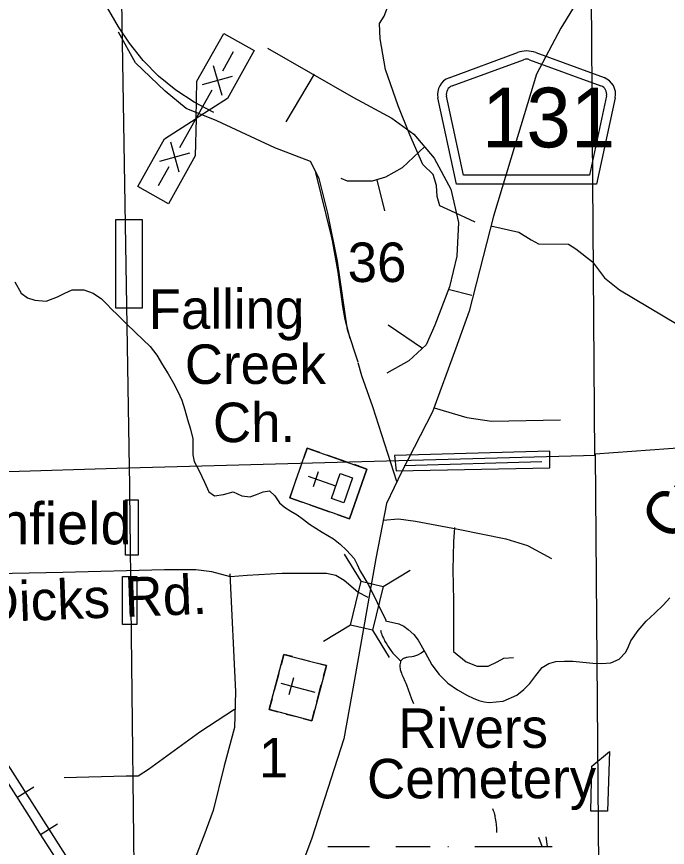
# Model space of a CAD drawing. Extents: x 2480962 to 2688785, y 277103 to 599240.
# Drawn here: x 2542680 to 2550088, y 460329 to 469792 of the extents above; entities that cross this region are included whole.
import ezdxf

# ---------------------------------------------------------------- set-up
doc = ezdxf.new("R2010")
doc.units = 0
for name, color, linetype in [('Bridges', 7, 'Continuous'), ('Communities and Subdivisions Names without Post Office', 7, 'Continuous'), ('County Routes Highway Center Lines', 7, 'Continuous'), ('Culture', 7, 'Continuous'), ('Culture Text', 7, 'Continuous'), ('Level 31', 7, 'Continuous'), ('Local Roads Improved', 7, 'Continuous'), ('Local Roads Paved', 7, 'Continuous'), ('Local Roads Related Cells', 7, 'Continuous'), ('Local Roads Related Text', 7, 'Continuous'), ('Narrow Canals Text', 7, 'Continuous'), ('Narrow River Creek and Branch and Slough', 7, 'Continuous'), ('Railroads', 7, 'Continuous'), ('Roadshields County Roads', 7, 'Continuous'), ('Section Lines', 7, 'Continuous'), ('Section Numbers', 7, 'Continuous'), ('Swamps', 7, 'Continuous'), ('Township and Range lines', 7, 'Continuous'), ('Uninventoried Roads and Features', 7, 'Continuous'), ('US Routes Highway Center Lines', 7, 'Continuous')]:
    doc.layers.add(name, color=color, linetype=linetype)

msp = doc.modelspace()

# ---------------------------------------------------------------- linework, layer by layer
at = {"layer": 'Bridges'}
for p, q in [((2546602.101, 463359.243), (2546413.271, 463668.137)), ((2546850.963, 463299.211), (2547159.857, 463488.041)), ((2546482.038, 462861.52), (2546173.144, 462672.69)), ((2546730.899, 462801.488), (2546919.729, 462492.594))]:
    msp.add_line(p, q, dxfattribs=at)
msp.add_lwpolyline([(2546482.038, 462861.52), (2546602.101, 463359.243), (2546850.963, 463299.211), (2546730.899, 462801.488)], close=True, dxfattribs=at)
at = {"layer": 'County Routes Highway Center Lines'}
msp.add_lwpolyline([(2550234.389, 471922.145), (2549677.277, 471016.839), (2549172.395, 470146.352), (2548876.429, 469658.879), (2548597.873, 469136.586), (2548354.137, 468335.738), (2548110.4, 467517.48), (2547831.844, 466438.076), (2547675.157, 466002.833), (2547414.011, 465289.033), (2547065.816, 464610.053), (2546891.718, 464244.449), (2546769.85, 463617.698), (2546526.114, 462242.328), (2546404.245, 461563.348), (2546038.641, 460431.715), (2545812.314, 459822.374)], dxfattribs=at)
at = {"layer": 'Culture'}
for p, q in [((2545989.074, 464877.365), (2545949.215, 464764.178)), ((2546130.556, 464827.541), (2545989.074, 464877.365)), ((2546441.82, 464717.929), (2546215.446, 464797.647)), ((2545859.531, 464509.508), (2545919.32, 464679.288)), ((2546668.193, 464638.21), (2546526.71, 464688.034)), ((2546313.875, 464444.926), (2546003.043, 464554.387)), ((2546057.607, 464439.755), (2546117.396, 464609.535)), ((2546468.898, 464072.276), (2546668.193, 464638.21)), ((2545829.637, 464424.618), (2545789.778, 464311.431)), ((2545789.778, 464311.431), (2545931.26, 464261.607)), ((2546016.151, 464231.713), (2546242.524, 464151.995)), ((2546327.414, 464122.1), (2546468.898, 464072.276)), ((2545722.763, 462527.478), (2545690.575, 462406.693)), ((2545819.391, 462501.727), (2545722.763, 462527.478)), ((2545916.019, 462475.977), (2546012.647, 462450.227)), ((2546205.902, 462398.726), (2546109.274, 462424.476)), ((2546173.714, 462277.941), (2546205.902, 462398.726)), ((2545664.825, 462310.065), (2545613.324, 462116.81)), ((2545687.389, 462200.562), (2546073.9, 462097.561)), ((2545782.423, 462071.747), (2545833.924, 462265.002)), ((2546096.463, 461988.058), (2546147.964, 462181.314)), ((2545587.574, 462020.182), (2545555.386, 461899.397)), ((2545555.386, 461899.397), (2545652.014, 461873.647)), ((2545748.642, 461847.897), (2545845.27, 461822.146)), ((2546038.525, 461770.646), (2546070.713, 461891.43)), ((2545941.897, 461796.396), (2546038.525, 461770.646))]:
    msp.add_line(p, q, dxfattribs=at)
for points in [[(2545789.778, 464311.431), (2545989.074, 464877.365), (2546668.193, 464638.21), (2546468.898, 464072.276)], [(2546264.051, 464303.443), (2546363.699, 464586.41), (2546505.183, 464536.586), (2546405.535, 464253.619)], [(2545555.386, 461899.397), (2545722.763, 462527.478), (2546205.902, 462398.726), (2546038.525, 461770.646)]]:
    msp.add_lwpolyline(points, close=True, dxfattribs=at)
at = {"layer": 'Level 31'}
for points in [[(2543810.419, 467481.047), (2544110.523, 467481.047), (2544110.523, 466470.933), (2543810.419, 466470.933)], [(2548748.781, 464650.307), (2548748.781, 464841.64), (2546982.37, 464793.807), (2546999.454, 464616.141)], [(2543919.548, 464286.904), (2544062.231, 464286.904), (2544062.231, 463658.996), (2543919.548, 463658.996)], [(2543883.749, 463412.557), (2544047.442, 463412.557), (2544047.442, 462866.55), (2543883.749, 462866.55)], [(2549227.764, 461252.936), (2549430.536, 461420.365), (2549407.572, 460741.202), (2549216.597, 460741.202)]]:
    msp.add_lwpolyline(points, close=True, dxfattribs=at)
at = {"layer": 'Local Roads Improved'}
for p, q in [((2546080.5, 468016.857), (2546260.121, 467292.099)), ((2546392.775, 466488.277), (2546338.77, 466882.236)), ((2547090.028, 464680.383), (2548659.997, 464722.435))]:
    msp.add_line(p, q, dxfattribs=at)
for points in [[(2546569.037, 465854.201), (2546445.219, 466222.316), (2546333.079, 467007.301), (2546220.938, 467553.986), (2546122.815, 467946.478), (2546024.692, 468142.724), (2545618.182, 468296.918), (2544959.356, 468605.305), (2544608.917, 468745.48), (2544370.618, 468941.726), (2544034.196, 469264.131), (2543837.95, 469614.57)], [(2548078.861, 467406.752), (2548396.986, 467337.387), (2548538.109, 467248.886), (2548621.826, 467203.439), (2548960.803, 467198.102), (2549045.534, 467145.145), (2549236.178, 466996.867), (2549373.865, 466816.814), (2549543.326, 466679.127), (2549882.249, 466477.892), (2550199.989, 466287.248), (2550443.589, 466234.291), (2551894.601, 466234.291), (2552477.124, 466244.882)], [(2546260.121, 467292.099), (2546277.117, 467220.658)], [(2546338.77, 466882.236), (2546277.935, 467217.062)], [(2546475.168, 466126.139), (2546418.224, 466341.212), (2546392.775, 466488.277)], [(2547433.471, 465336.958), (2547804.924, 465227.068), (2548085.276, 465185.015), (2548870.26, 465199.033)], [(2546683.518, 463173.493), (2546564.369, 463236.572), (2546410.175, 463369.739), (2546312.052, 463425.809), (2546206.92, 463446.836), (2545702.288, 463446.836), (2545302.787, 463425.809), (2545113.549, 463411.792), (2544903.286, 463467.862), (2544721.057, 463488.888), (2544363.609, 463488.888), (2543207.159, 463460.853), (2542239.946, 463439.827), (2541910.533, 463439.827), (2541714.287, 463439.827), (2541553.084, 463509.915), (2541384.874, 463713.17), (2541090.504, 464140.706), (2540964.346, 464322.934), (2540859.214, 464386.013), (2540768.1, 464407.04), (2540691.003, 464407.04), (2540508.775, 464322.934)]]:
    msp.add_lwpolyline(points, dxfattribs=at)
at = {"layer": 'Local Roads Paved'}
for p, q in [((2546066.745, 469137.972), (2545744.34, 468591.287)), ((2546781.641, 467932.461), (2546867.336, 467577.713)), ((2547592.046, 466686.786), (2547861.319, 466616.974)), ((2547300.292, 466012.053), (2546907.799, 466278.387))]:
    msp.add_line(p, q, dxfattribs=at)
for points in [[(2545534.077, 469432.342), (2546515.307, 468871.639), (2546949.852, 468633.34), (2547202.168, 468451.111), (2547434.24, 468179.341), (2547621.903, 467827.429), (2547710.404, 467444.723), (2547692.784, 467063.371), (2547608.678, 466712.931), (2547440.467, 466278.387), (2547342.344, 466054.105), (2547146.098, 465871.877), (2546893.782, 465731.701)], [(2547328.327, 468310.935), (2547068.282, 468070.604), (2546878.12, 467962.872), (2546725.571, 467918.443), (2546445.219, 467918.443), (2546375.131, 467946.478)], [(2547008.34, 464497.323), (2546735.928, 465347.157), (2546611.108, 465700.815), (2546569.501, 465846.438)], [(2546846.88, 464057.348), (2547027.175, 464071.217), (2547221.34, 464043.479), (2547706.752, 463953.331), (2548247.64, 463842.38), (2548497.281, 463766.101), (2548767.725, 463620.477)], [(2547665.146, 463974.135), (2547651.277, 463807.708), (2547644.342, 463488.722), (2547651.277, 463142), (2547651.277, 462892.359), (2547651.277, 462691.26), (2547651.277, 462559.505), (2547796.9, 462441.619), (2547921.721, 462393.078), (2548046.541, 462393.078), (2548150.558, 462441.619), (2548226.837, 462483.226), (2548337.788, 462490.16)], [(2545107.833, 463443.768), (2545171.781, 462100.874), (2545161.123, 461695.875), (2545043.886, 461258.901), (2544915.991, 460747.323), (2544809.413, 460459.56), (2544724.149, 460235.744), (2544689.949, 460204.619)], [(2545161.123, 461898.374), (2544766.781, 461642.585), (2544180.597, 461216.27), (2544063.36, 461141.664), (2543924.808, 461141.664), (2543221.387, 461120.349)]]:
    msp.add_lwpolyline(points, dxfattribs=at)
at = {"layer": 'Local Roads Related Cells'}
for p, q in [((2544731.181, 469054.639), (2545036.808, 469599.815)), ((2545036.808, 469599.815), (2545385.721, 469404.213)), ((2545027.888, 469174.909), (2545150.139, 469392.979)), ((2545385.721, 469404.213), (2545080.093, 468859.037)), ((2544918.852, 469236.034), (2545014.672, 468895.713)), ((2544796.601, 469017.964), (2545136.923, 469113.783)), ((2544722.261, 468629.734), (2544731.181, 469054.639)), ((2544538.885, 468302.629), (2544905.637, 468956.838)), ((2545080.093, 468859.037), (2544722.261, 468629.734)), ((2544364.429, 468400.43), (2544722.261, 468629.734)), ((2544722.261, 468629.734), (2544713.341, 468204.828)), ((2544058.801, 467855.254), (2544364.429, 468400.43)), ((2544429.849, 468363.754), (2544525.669, 468023.433)), ((2544309.612, 468144.555), (2544649.934, 468240.374)), ((2544713.341, 468204.828), (2544407.714, 467659.652)), ((2544294.382, 467866.488), (2544416.634, 468084.558)), ((2544407.714, 467659.652), (2544058.801, 467855.254))]:
    msp.add_line(p, q, dxfattribs=at)
at = {"layer": 'Narrow River Creek and Branch and Slough'}
for points in [[(2542660.107, 466772.511), (2542730.986, 466641.793), (2542803.364, 466589.28), (2542885.593, 466560.011), (2543017.837, 466551.731), (2543143.829, 466601.396), (2543227.669, 466640.112), (2543311.641, 466678.167), (2543443.709, 466680.438), (2543551.557, 466642.13), (2543646.214, 466578.371), (2543705.701, 466515.764), (2543764.548, 466453.746), (2543823.628, 466396.709), (2543928.359, 466295.599), (2544033.09, 466194.488), (2544116.337, 466114.119), (2544199.584, 466033.749), (2544276.019, 465934.334), (2544340.46, 465825.072), (2544404.041, 465721.269), (2544465.486, 465616.122), (2544516.664, 465521.347), (2544558.553, 465422.454), (2544593.151, 465312.511), (2544625.646, 465201.952), (2544658.043, 465092.252), (2544687.457, 464981.36), (2544683.849, 464881.025), (2544686.149, 464801.463), (2544702.341, 464723.018), (2544756.93, 464618.407), (2544817.243, 464487.506), (2544866.637, 464377.528), (2544930.822, 464331.134), (2545036.212, 464348.779), (2545146.708, 464377.067), (2545242.589, 464331.218), (2545337.854, 464322.302), (2545411.371, 464349.954), (2545485.862, 464380.019), (2545558.67, 464389.43), (2545619.065, 464331.82), (2545671.898, 464254.162), (2545730.889, 464202.402), (2545803.053, 464158.704), (2545875.02, 464115.162), (2545944.239, 464063.146), (2546014.132, 464012.005), (2546085.961, 463965.304), (2546158.352, 463919.491), (2546222.497, 463881.275), (2546286.457, 463842.531), (2546364.164, 463781.41), (2546436.577, 463713.175), (2546522.686, 463619.66), (2546556.374, 463551.892), (2546588.369, 463483.575), (2546629.176, 463413.035), (2546669.989, 463342.486), (2546684.205, 463317.598)], [(2546684.205, 463317.598), (2546882.486, 462915.864), (2546878.899, 462908.684), (2547031.86, 462873.734), (2547087.902, 462847.125), (2547138.571, 462812.238), (2547199.693, 462753.276), (2547251.623, 462687.523), (2547329.654, 462547.142), (2547407.671, 462406.933), (2547491.23, 462297.424), (2547589.515, 462199.838), (2547696.828, 462122.611), (2547811.767, 462058.409), (2547876.251, 462028.697), (2547943.099, 462002.849), (2548001.109, 461985.998), (2548059.276, 461977.595), (2548216.912, 461995.063), (2548372.445, 462063.47), (2548454.58, 462125.088), (2548523.978, 462194.803), (2548589.703, 462288.26), (2548662.372, 462379.303), (2548737.16, 462424.819), (2548819.795, 462445.341), (2548914.962, 462450.988), (2549009.972, 462448.611), (2549123.774, 462437.603), (2549237.568, 462426.139), (2549340.518, 462421.652), (2549443.593, 462429.683), (2549539.793, 462473.513), (2549615.896, 462554.028), (2549644.729, 462618.501), (2549671.891, 462681.652), (2549755.14, 462797.545), (2549847.801, 462906.333), (2549944.857, 462997.143), (2550040.265, 463089.079), (2550116.067, 463171.646)], [(2546821.149, 462801.961), (2546824.573, 462790.434), (2546827.767, 462780.453), (2546833.786, 462763.186), (2546838.646, 462750.371), (2546846.468, 462731.31), (2546854.892, 462712.365), (2546862.472, 462696.556), (2546869.441, 462682.993), (2546882.342, 462659.758), (2546892.559, 462642.656), (2546908.666, 462617.34), (2546925.594, 462592.197), (2546939.513, 462572.608), (2546952.048, 462556.047), (2546963.343, 462541.968), (2546973.513, 462529.942), (2546992.05, 462509.501), (2547006.65, 462494.627), (2547018.038, 462483.701), (2547035.893, 462467.642), (2547054.758, 462451.927)], [(2547313.014, 462567.632), (2547320.189, 462564.042), (2547318.624, 462562.803), (2547300.186, 462551.084), (2547286.163, 462542.7), (2547243.877, 462518.509), (2547232.636, 462512.98), (2547221.304, 462508.833), (2547210.11, 462505.703), (2547199.222, 462503.31), (2547178.107, 462499.825), (2547140.62, 462494.886), (2547126.948, 462492.738), (2547115.377, 462490.46), (2547105.651, 462488.045), (2547097.511, 462485.529), (2547090.717, 462482.966), (2547085.051, 462480.412), (2547075.841, 462475.152), (2547069.587, 462470.469), (2547065.301, 462466.497), (2547059.573, 462459.736), (2547054.758, 462451.927), (2547051.142, 462444.243), (2547048.252, 462436.676), (2547044.273, 462421.696), (2547042.345, 462407.307), (2547041.981, 462393.549), (2547042.793, 462380.446), (2547044.473, 462368.006), (2547046.776, 462356.227), (2547052.745, 462333.903), (2547059.424, 462314.193), (2547066.124, 462296.881), (2547079.114, 462266.601), (2547099.458, 462221.786), (2547108.985, 462199.918), (2547117.45, 462178.574), (2547155.53, 462073.333), (2547175.085, 462020.891), (2547195.9, 461968.944)], [(2548095.596, 460770.463), (2548104.846, 460748.787), (2548111.232, 460732.296), (2548115.57, 460719.772), (2548118.51, 460710.284), (2548120.513, 460703.109), (2548123.158, 460692.248), (2548125.322, 460681.262), (2548129.008, 460658.295), (2548134.284, 460618.041), (2548137.432, 460587.802), (2548141.2, 460542.376), (2548144.254, 460496.875)]]:
    msp.add_lwpolyline(points, dxfattribs=at)
at = {"layer": 'Railroads'}
for p, q in [((2542876.945, 461015.465), (2542682.962, 460891.89)), ((2543145.584, 460593.762), (2542951.601, 460470.188))]:
    msp.add_line(p, q, dxfattribs=at)
for points in [[(2535189.55, 474029.408), (2536089.7, 471644.944), (2536291.253, 471185.4), (2536531.488, 470762.342), (2552586.883, 445559.036), (2552586.884, 445559.036), (2553075.384, 444874.143), (2553427.841, 444460.531), (2556691.947, 440882.519), (2556841.764, 440734.641), (2557006.218, 440603.234), (2557183.506, 440489.737), (2557371.687, 440395.394), (2557568.699, 440321.239), (2557735.519, 440276.028), (2568072.12, 437946.462), (2568887.934, 437807.005), (2569361.53, 437765.755), (2570495.789, 437701.245), (2571983.523, 437694.622), (2573132.142, 437796.523), (2616563.163, 443432.973)], [(2536531.488, 470762.342), (2552586.883, 445559.036), (2552586.884, 445559.036), (2553075.384, 444874.143), (2553427.841, 444460.531), (2556691.947, 440882.519), (2556841.764, 440734.641), (2557006.218, 440603.234), (2557183.506, 440489.737), (2557371.687, 440395.394), (2557568.699, 440321.239), (2557735.519, 440276.028), (2568072.12, 437946.462), (2568887.934, 437807.005), (2569361.53, 437765.755), (2570495.789, 437701.245), (2571983.523, 437694.622), (2573132.142, 437796.523), (2616563.163, 443432.973)]]:
    msp.add_lwpolyline(points, dxfattribs=at)
at = {"layer": 'Roadshields County Roads'}
for p, q in [((2547602.477, 469095.945), (2548381.852, 469382.282)), ((2548588.765, 469382.282), (2549366.787, 469096.442)), ((2547636.963, 469002.079), (2548450.823, 469301.086)), ((2548519.794, 469301.086), (2549332.302, 469002.575)), ((2547686.449, 467884.119), (2547475.892, 468866.29)), ((2547767.283, 467984.119), (2547573.67, 468887.252)), ((2549395.595, 468887.748), (2549201.875, 467984.119)), ((2549493.373, 468866.788), (2549282.709, 467884.119)), ((2549201.875, 467984.119), (2547767.283, 467984.119)), ((2549282.709, 467884.119), (2547686.449, 467884.119))]:
    msp.add_line(p, q, dxfattribs=at)
for centre, radius, start, end in [((2548485.309, 469100.685), 300, 69.8269806, 110.1730139), ((2548485.308, 469207.22), 100, 69.8269876, 110.1729839), ((2547671.448, 468908.214), 200, 110.1729839, 192.0998896), ((2549297.816, 468908.71), 200, 347.9000917, 69.8270083), ((2547671.448, 468908.214), 100, 110.1729839, 192.0998896), ((2549297.816, 468908.71), 100, 347.9000932, 69.8269876)]:
    msp.add_arc(centre, radius, start, end, dxfattribs=at)
at = {"layer": 'Section Lines'}
for p, q in [((2543965.349, 464652.529), (2543875.69, 469964.055)), ((2544027.913, 459386.313), (2543964.503, 464723.862))]:
    msp.add_line(p, q, dxfattribs=at)
at = {"layer": 'Swamps'}
for p, q in [((2549155.078, 464792.238), (2549267.512, 464795.265)), ((2547895.457, 460339.2), (2548495.454, 460339.21))]:
    msp.add_line(p, q, dxfattribs=at)
for points in [[(2548661.134, 460340.2), (2548623.009, 460439.907)], [(2548723.456, 460339.278), (2548706.533, 460448.052)], [(2546223.926, 460339.172), (2546695.461, 460339.18)], [(2546995.46, 460339.185), (2547386.826, 460339.191)], [(2547590.27, 460339.195), (2547595.458, 460339.195)], [(2548495.454, 460339.21), (2548777.173, 460339.215)]]:
    msp.add_lwpolyline(points, dxfattribs=at)
at = {"layer": 'Township and Range lines'}
for p, q in [((2549221.264, 470150.934), (2549257.995, 464787.829)), ((2554589.04, 465187.392), (2549267.406, 464809.423)), ((2543947.212, 464652.04), (2549273.161, 464795.417)), ((2549267.406, 464809.423), (2549306.771, 459514.808)), ((2538737.603, 464487.596), (2543947.212, 464652.04))]:
    msp.add_line(p, q, dxfattribs=at)
at = {"layer": 'Uninventoried Roads and Features'}
msp.add_line((2543841.296, 469676.145), (2542738.403, 471566.322), dxfattribs=at)
for points in [[(2547899.73, 467451.976), (2547621.264, 467578.36), (2547498.505, 467637.127), (2547468.878, 467742.481), (2547457.951, 467869.496), (2547420.14, 467993.939), (2547303.704, 468106.853), (2547154.605, 468444.612), (2547024.889, 468777.051), (2546879.7, 469188.185), (2546816.871, 469539.584), (2546812.463, 469713.039), (2546862.295, 469797.157), (2546893.038, 469875.033), (2546901.088, 469936.935)], [(2544923.138, 468699.999), (2544700.133, 468815.509), (2544490.423, 468953.698), (2544296.306, 469113.05), (2544119.91, 469291.819), (2543963.167, 469488.048), (2543841.296, 469676.145)]]:
    msp.add_lwpolyline(points, dxfattribs=at)
at = {"layer": 'US Routes Highway Center Lines'}
msp.add_lwpolyline([(2537341.586, 469291.003), (2538342.082, 467731.72), (2538693.32, 467178.254), (2539033.914, 466646.075), (2539108.42, 466518.352), (2540034.411, 465086.791), (2540577.233, 464208.696), (2540917.827, 463671.195), (2541013.62, 463538.151), (2541902.358, 462122.555), (2542407.928, 461324.287), (2542823.027, 460680.35), (2542950.75, 460472.801), (2543663.87, 459360.547), (2543988.499, 458849.655)], dxfattribs=at)

# ---------------------------------------------------------------- texts
at = {"layer": 'Communities and Subdivisions Names without Post Office'}
msp.add_text('Winfield', height=475, rotation=0.0009472, dxfattribs=at).set_placement((2541729.22, 463780.476))
at = {"layer": 'Culture Text'}
for s, rotation, p in [('Falling', 0.0570222, (2544183.196, 466235.014)), ('Creek', 0.05155, (2544594.768, 465607.318)), ('Ch.', 0.05155, (2544915.374, 464944.04)), ('Rivers', 0.0515556, (2547023.7, 461461.055)), ('Cemetery', 0.0515556, (2546669.469, 460886.588))]:
    msp.add_text(s, height=450, rotation=rotation, dxfattribs=at).set_placement(p)
at = {"layer": 'Local Roads Related Text'}
msp.add_text('Dicks Rd.', height=450, rotation=2.2404306, dxfattribs=at).set_placement((2542279.878, 462889.307))
at = {"layer": 'Narrow Canals Text'}
msp.add_text('Cr.', height=500, rotation=52.6968944, dxfattribs=at).set_placement((2550148.14, 463787.904))
at = {"layer": 'Roadshields County Roads'}
msp.add_text('131', height=680, dxfattribs=at).set_placement((2547977.063, 468302.403))
at = {"layer": 'Section Numbers'}
for s, rotation, p in [('36', 359.9794417, (2546448.546, 466768.354)), ('1', 359.9794583, (2545438.311, 461124.986))]:
    msp.add_text(s, height=450, rotation=rotation, dxfattribs=at).set_placement(p)

doc.saveas('drawing.dxf')
